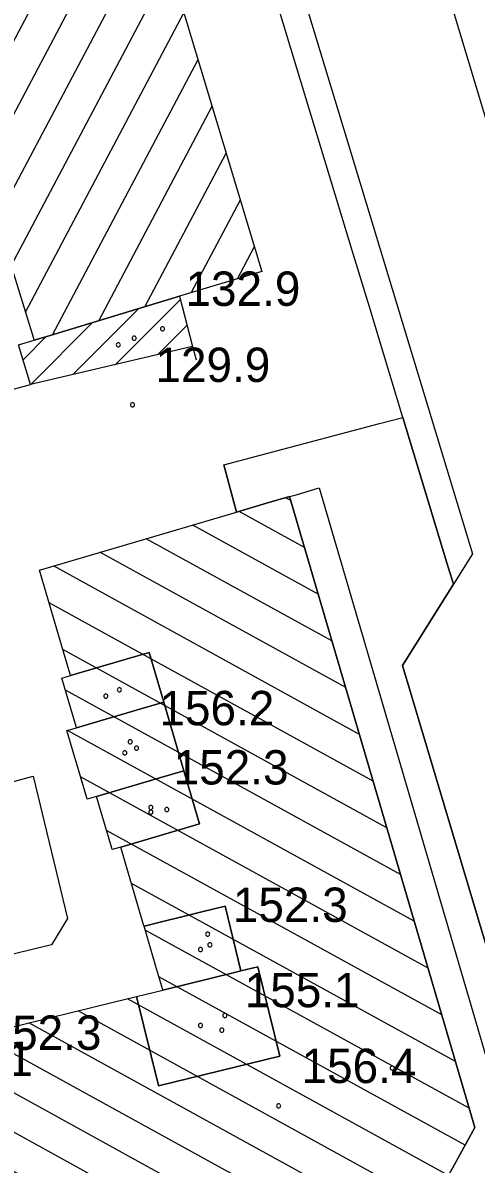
# Model space of a CAD drawing. Extents: x 513373 to 514978, y 5038576 to 5040180.
# Drawn here: x 513625.28 to 513645.09, y 5038613.29 to 5038663.13 of the extents above; entities that cross this region are included whole.
import ezdxf

# ---------------------------------------------------------------- set-up
doc = ezdxf.new("R2010")
doc.units = 0
for name, color, linetype in [('2010300', 7, 'Continuous'), ('3010204', 7, 'Continuous'), ('B1211', 7, 'Continuous'), ('C1131', 7, 'Continuous'), ('C12211', 7, 'Continuous'), ('C21195', 7, 'Continuous'), ('C2911', 7, 'Continuous'), ('C2912', 7, 'Continuous'), ('CAMP_C12211', 7, 'Continuous'), ('CAMP_C21195', 7, 'Continuous'), ('Default', 7, 'Continuous'), ('F12107', 7, 'Continuous'), ('F12131', 7, 'Continuous'), ('F12132', 7, 'Continuous'), ('TOP920', 7, 'Continuous')]:
    doc.layers.add(name, color=color, linetype=linetype)

# ---------------------------------------------------------------- blocks, each defined once
blk = doc.blocks.new('CAMP_13884420')
at = {"layer": 'CAMP_C12211'}
for p, q in [((3.521, 4.937), (14.114, 24.943)), ((7.011, 14.734), (12.456, 25.017)), ((6.386, 16.759), (10.427, 24.39)), ((5.76, 18.783), (8.397, 23.763)), ((5.135, 20.807), (6.368, 23.136)), ((3.486, 1.666), (14.73, 22.901)), ((3.759, -1.025), (15.346, 20.859)), ((-1.731, -14.6), (15.962, 18.817)), ((0.298, -13.973), (16.578, 16.775)), ((2.327, -13.346), (17.194, 14.733)), ((0.551, 2.533), (5.93, 12.693)), ((4.356, -12.719), (17.811, 12.691)), ((5.93, 12.693), (6.065, 12.948)), ((-3.398, -1.719), (4.036, 12.321)), ((-4.99, -1.52), (2.007, 11.694)), ((-5.604, 0.525), (-0.023, 11.066)), ((6.386, -12.092), (18.427, 10.65)), ((-7.523, 0.107), (-2.052, 10.439)), ((-12.88, -6.805), (-4.081, 9.812)), ((-13.494, -4.76), (-6.11, 9.185)), ((-13.916, -2.351), (-8.14, 8.558)), ((8.415, -11.465), (19.043, 8.608)), ((-15.597, -2.321), (-10.169, 7.931)), ((-19.19, -5.901), (-12.198, 7.304)), ((-19.815, -3.877), (-14.228, 6.677)), ((10.444, -10.838), (19.659, 6.566)), ((-20.441, -1.852), (-16.257, 6.05)), ((-21.066, 0.172), (-18.286, 5.423)), ((-21.692, 2.196), (-20.315, 4.796)), ((2.57, 3.14), (3.521, 4.937)), ((12.474, -10.211), (20.276, 4.524)), ((-1.379, -1.113), (0.542, 2.515)), ((13.962, -10.605), (20.892, 2.482)), ((2.658, 0.1), (2.988, 0.725)), ((0.639, -0.506), (1.156, 0.47)), ((14.588, -12.629), (21.508, 0.441)), ((-16.063, -16.022), (-7.934, -0.671)), ((-7.819, -16.481), (0.639, -0.506)), ((-9.849, -17.109), (-1.379, -1.113)), ((-5.416, -2.326), (-5.086, -1.702)), ((-4.529, -3.857), (-3.398, -1.719)), ((15.762, -13.618), (22.124, -1.601)), ((-7.435, -2.933), (-7.104, -2.309)), ((-5.79, -15.854), (1.428, -2.221)), ((-3.761, -15.227), (3.076, -2.314)), ((-15.437, -18.047), (-7.474, -3.007)), ((-17.452, -5.824), (-16.246, -3.547)), ((17.782, -13.008), (22.74, -3.643)), ((-15.509, -5.36), (-15.178, -4.735)), ((-11.878, -17.736), (-4.998, -4.741)), ((-13.907, -18.363), (-6.86, -5.053)), ((-18.564, -7.925), (-17.452, -5.824)), ((-17.939, -9.949), (-15.824, -5.955)), ((19.802, -12.399), (23.356, -5.685)), ((-16.688, -13.998), (-13.072, -7.168)), ((-17.314, -11.974), (-15.09, -7.775)), ((21.822, -11.789), (23.972, -7.727)), ((23.842, -11.179), (24.589, -9.769))]:
    blk.add_line(p, q, dxfattribs=at)
blk = doc.blocks.new('CAMP_71B7BAA1')
at = {"layer": 'CAMP_C12211'}
for p, q in [((9.95, 21.918), (9.723, 22.043)), ((10.549, 19.876), (7.693, 21.447)), ((11.149, 17.835), (5.663, 20.851)), ((11.748, 15.794), (3.634, 20.255)), ((12.348, 13.753), (1.605, 19.659)), ((12.947, 11.711), (-0.425, 19.063)), ((13.547, 9.67), (-0.607, 17.451)), ((14.146, 7.629), (-0.008, 15.41)), ((14.745, 5.587), (0.103, 13.637)), ((15.345, 3.546), (0.185, 11.881)), ((15.944, 1.505), (0.764, 9.85)), ((16.544, -0.536), (1.901, 7.514)), ((17.143, -2.578), (2.99, 5.203)), ((17.743, -4.619), (3.59, 3.162)), ((17.563, -6.232), (4.189, 1.121)), ((16.843, -7.548), (2.813, 0.165)), ((15.297, -8.41), (0.661, -0.364)), ((13.146, -8.939), (-1.491, -0.892)), ((8.843, -9.996), (-7.1, -1.232)), ((10.994, -9.468), (-4.284, -1.068)), ((6.691, -10.525), (-9.252, -1.761)), ((4.539, -11.054), (-10.74, -2.654)), ((2.388, -11.583), (-12.437, -3.433)), ((0.236, -12.112), (-14.4, -4.066)), ((-1.915, -12.641), (-16.551, -4.595)), ((-4.067, -13.17), (-18.703, -5.124)), ((-6.218, -13.699), (-20.854, -5.653)), ((-8.369, -14.228), (-21.878, -6.801)), ((-10.521, -14.757), (-21.418, -8.766)), ((-12.673, -15.286), (-20.957, -10.731)), ((-14.824, -15.814), (-20.496, -12.697)), ((-16.976, -16.343), (-20.035, -14.662)), ((-19.128, -16.872), (-19.574, -16.627))]:
    blk.add_line(p, q, dxfattribs=at)
blk = doc.blocks.new('CAMP_03B43D88')
at = {"layer": 'CAMP_C21195'}
for p, q in [((-1.374, -1.374), (1.504, 1.504)), ((0.47, -0.945), (3.319, 1.905)), ((-3.218, -1.803), (-0.521, 0.893)), ((2.313, -0.515), (3.609, 0.78)), ((-3.555, -0.726), (-2.546, 0.282))]:
    blk.add_line(p, q, dxfattribs=at)
blk = doc.blocks.new('08020400')
at = {"layer": 'Default'}
for p, q in [((-0.086, 0.028), (-0.09, 0)), ((-0.09, 0), (-0.086, -0.028)), ((-0.073, 0.053), (-0.086, 0.028)), ((-0.053, 0.073), (-0.073, 0.053)), ((-0.028, 0.086), (-0.053, 0.073)), ((0, 0.09), (-0.028, 0.086)), ((0.028, 0.086), (0, 0.09)), ((0.053, 0.073), (0.028, 0.086)), ((0.073, 0.053), (0.053, 0.073)), ((0.086, 0.028), (0.073, 0.053)), ((0.09, 0), (0.086, 0.028)), ((0.086, -0.028), (0.09, 0)), ((-0.086, -0.028), (-0.073, -0.053)), ((-0.073, -0.053), (-0.053, -0.073)), ((-0.053, -0.073), (-0.028, -0.086)), ((-0.028, -0.086), (0, -0.09)), ((0, -0.09), (0.028, -0.086)), ((0.028, -0.086), (0.053, -0.073)), ((0.053, -0.073), (0.073, -0.053)), ((0.073, -0.053), (0.086, -0.028))]:
    blk.add_line(p, q, dxfattribs=at)
blk = doc.blocks.new('NSIMB25')
at = {"layer": 'Default'}
for p, q in [((-0.086, 0.028), (-0.09, 0)), ((-0.09, 0), (-0.086, -0.028)), ((-0.073, 0.053), (-0.086, 0.028)), ((-0.053, 0.073), (-0.073, 0.053)), ((-0.028, 0.086), (-0.053, 0.073)), ((0, 0.09), (-0.028, 0.086)), ((0.028, 0.086), (0, 0.09)), ((0.053, 0.073), (0.028, 0.086)), ((0.073, 0.053), (0.053, 0.073)), ((0.086, 0.028), (0.073, 0.053)), ((0.09, 0), (0.086, 0.028)), ((0.086, -0.028), (0.09, 0)), ((-0.086, -0.028), (-0.073, -0.053)), ((-0.073, -0.053), (-0.053, -0.073)), ((-0.053, -0.073), (-0.028, -0.086)), ((-0.028, -0.086), (0, -0.09)), ((0, -0.09), (0.028, -0.086)), ((0.028, -0.086), (0.053, -0.073)), ((0.053, -0.073), (0.073, -0.053)), ((0.073, -0.053), (0.086, -0.028))]:
    blk.add_line(p, q, dxfattribs=at)
blk = doc.blocks.new('A$C3704598A')
at = {"layer": '2010300'}
blk.add_lwpolyline([(234.926, -783.811), (239.656, -782.696), (240.683, -782.453), (243.098, -778.106), (275.603, -770.148), (276.632, -769.896), (275.194, -774.344), (275.191, -774.351), (276.759, -773.983), (277.346, -773.772), (279.141, -769.287), (276.899, -761.303), (276.167, -762.574), (274.781, -764.98), (274.477, -763.965), (273.197, -759.683), (268.828, -745.067), (271.049, -741.525), (270.763, -740.582), (268.839, -734.233), (267.364, -729.37)], dxfattribs=at)
at = {"layer": '3010204'}
blk.add_lwpolyline([(244.141, -752.219), (244.566, -752.105), (245.406, -751.878), (252.691, -749.907), (254.191, -756.119), (253.491, -757.273), (247.115, -758.812), (246.222, -759.027), (243.621, -759.655), (242.406, -755.224), (242.993, -754.798), (243.479, -754.26), (243.841, -753.631), (244.066, -752.941), (244.141, -752.219)], dxfattribs=at)
at = {"layer": 'B1211'}
for points in [[(283.252, -756.933), (264.211, -693.769), (259.814, -679.302), (257.474, -671.601), (257.45, -671.522), (257.371, -671.263), (257.393, -670.826), (257.636, -670.153), (257.934, -669.828), (258.151, -669.592), (258.407, -669.448), (270.456, -665.66), (287.698, -660.31)], [(270.537, -767.892), (271.988, -765.243), (263.897, -737.693), (262.891, -737.988), (261.58, -738.373), (261.564, -738.312), (261.028, -736.302), (267.826, -734.501), (268.839, -734.233), (270.763, -740.582), (271.049, -741.525), (268.828, -745.067), (273.197, -759.683)]]:
    blk.add_lwpolyline(points, dxfattribs=at)
blk.add_lwpolyline([(271.884, -740.192), (271.049, -741.525), (270.763, -740.582), (268.839, -734.233), (267.364, -729.37), (266.632, -726.953), (261.45, -709.862), (260.968, -708.309), (257.279, -696.425), (255.429, -690.383), (255.68, -690.305), (255.736, -690.288), (256.672, -689.963), (260.111, -701.391), (266.569, -722.666)], close=True, dxfattribs=at)
at = {"layer": 'C1131'}
for points in [[(253.285, -730.7), (252.739, -730.865), (252.718, -730.797), (251.493, -726.833), (251.152, -725.672), (247.781, -714.213), (248.265, -714.071), (245.205, -703.637), (244.029, -699.829), (243.87, -699.317), (242.358, -694.422), (250.722, -691.837), (251.724, -691.528), (253.122, -696.162), (253.143, -696.229), (253.412, -697.122), (257.134, -709.456), (257.16, -709.544), (257.615, -711.051), (262.688, -727.862), (259.089, -728.949), (258.083, -729.252)], [(259.656, -731.147), (252.576, -732.796), (252.575, -732.793), (252.056, -731.071), (252.739, -730.865), (253.285, -730.7), (258.083, -729.252), (259.089, -728.949)], [(258.401, -746.668), (257.396, -746.963), (254.583, -747.79), (254.565, -747.729), (253.946, -745.619), (254.324, -745.508), (256.759, -744.792), (257.764, -744.497)], [(259.281, -749.663), (258.276, -749.958), (255.463, -750.785), (255.048, -750.907), (255.03, -750.846), (254.169, -747.911), (254.583, -747.79), (257.396, -746.963), (258.401, -746.668)], [(256.524, -753), (256.146, -753.111), (256.128, -753.05), (255.463, -750.785), (258.276, -749.958), (259.281, -749.663), (259.964, -751.99)], [(261.767, -758.405), (261.486, -758.474), (258.357, -759.242), (258.352, -759.226), (258.056, -758.217), (257.537, -756.448), (260.054, -755.828), (261.073, -755.577)], [(257.212, -759.524), (258.357, -759.242), (261.486, -758.474), (261.767, -758.405), (262.505, -758.224), (263.464, -762.124), (258.171, -763.425), (258.167, -763.409)]]:
    blk.add_lwpolyline(points, close=True, dxfattribs=at)
for points in [[(272.425, -768.805), (271.852, -768.961), (271.43, -769.053), (233.651, -778.34), (233.647, -778.325), (230.763, -766.025), (230.903, -765.991), (231.922, -765.74), (234.5, -776.734), (234.504, -776.749), (247.715, -773.503), (250.181, -772.896), (270.537, -767.892), (271.988, -765.243), (263.897, -737.693), (264.178, -737.61), (265.184, -737.315), (273.432, -765.399)], [(251.567, -760.911), (256.193, -759.774), (257.212, -759.524), (258.167, -763.409), (258.171, -763.425), (263.464, -762.124), (262.505, -758.224), (261.767, -758.405), (261.073, -755.577), (260.054, -755.828), (257.537, -756.448), (257.532, -756.432), (256.685, -753.549), (256.524, -753), (259.964, -751.99), (259.281, -749.663), (258.401, -746.668), (257.764, -744.497), (256.759, -744.792), (254.324, -745.508), (254.306, -745.447), (254.094, -744.727), (252.971, -740.902), (261.58, -738.373), (262.891, -737.988), (263.897, -737.693), (271.988, -765.243), (270.537, -767.892)]]:
    blk.add_lwpolyline(points, dxfattribs=at)
at = {"layer": 'C12211'}
for points in [[(257.615, -711.051), (262.688, -727.862), (259.089, -728.949), (258.083, -729.252), (253.285, -730.7), (252.739, -730.865), (252.718, -730.797), (251.493, -726.833)], [(251.567, -760.911), (256.193, -759.774), (257.212, -759.524), (258.357, -759.242), (258.352, -759.226), (258.056, -758.217), (257.537, -756.448), (257.532, -756.432), (256.685, -753.549), (256.524, -753), (256.146, -753.111), (256.128, -753.05), (255.463, -750.785), (255.048, -750.907), (255.03, -750.846), (254.169, -747.911), (254.583, -747.79), (254.565, -747.729), (253.946, -745.619), (254.324, -745.508), (254.306, -745.447), (254.094, -744.727), (252.971, -740.902), (261.58, -738.373), (262.891, -737.988), (263.897, -737.693), (271.988, -765.243), (270.537, -767.892)]]:
    blk.add_lwpolyline(points, dxfattribs=at)
at = {"layer": 'C21195'}
blk.add_lwpolyline([(259.656, -731.147), (252.576, -732.796), (252.575, -732.793), (252.056, -731.071), (252.739, -730.865), (253.285, -730.7), (258.083, -729.252), (259.089, -728.949)], close=True, dxfattribs=at)
at = {"layer": 'C2911'}
blk.add_lwpolyline([(249.635, -733.593), (252.576, -732.796)], dxfattribs=at)
at = {"layer": 'C2912'}
for points in [[(259.656, -731.147), (259.811, -731.729)], [(261.028, -736.302), (261.564, -738.312), (261.58, -738.373)]]:
    blk.add_lwpolyline(points, dxfattribs=at)
at = {"layer": 'CAMP_C12211'}
for name, p in [('CAMP_13884420', (237.772, -717.007)), ('CAMP_71B7BAA1', (253.999, -759.787))]:
    blk.add_blockref(name, p, dxfattribs=at)
at = {"layer": 'CAMP_C21195'}
blk.add_blockref('CAMP_03B43D88', (255.805, -730.99), dxfattribs=at)
at = {"layer": 'F12107'}
for p in [(258.346, -730.366), (257.033, -733.689), (257.208, -748.679), (257.829, -751.266), (260.415, -757.267), (260.933, -760.992), (263.416, -764.303)]:
    blk.add_blockref('08020400', p, dxfattribs=at)
at = {"layer": 'F12131'}
for p in [(256.411, -731.07), (256.457, -746.127), (256.928, -748.399), (258.527, -751.363), (260.315, -756.797), (261.068, -760.354)]:
    blk.add_blockref('NSIMB25', p, dxfattribs=at)
at = {"layer": 'F12132'}
for p in [(257.105, -730.78), (255.863, -746.403), (256.691, -748.886), (257.829, -751.473), (260.002, -757.474), (260.002, -760.785), (268.382, -762.647)]:
    blk.add_blockref('NSIMB25', p, dxfattribs=at)
at = {"layer": 'TOP920'}
for s, p in [('132.9', (259.346, -729.366)), ('129.9', (258.033, -732.689)), ('156.2', (258.208, -747.679)), ('152.3', (258.829, -750.266)), ('152.3', (261.415, -756.267)), ('155.1', (261.933, -759.992)), ('152.3', (250.655, -761.854)), ('156.1', (247.654, -762.992)), ('156.4', (264.416, -763.303))]:
    blk.add_text(s, height=1.5, dxfattribs=at).set_placement(p)

msp = doc.modelspace()

# ---------------------------------------------------------------- block references
at = {"layer": 'Default'}
msp.add_blockref('A$C3704598A', (513373.046, 5039380.14), dxfattribs=at)

doc.saveas('drawing.dxf')
